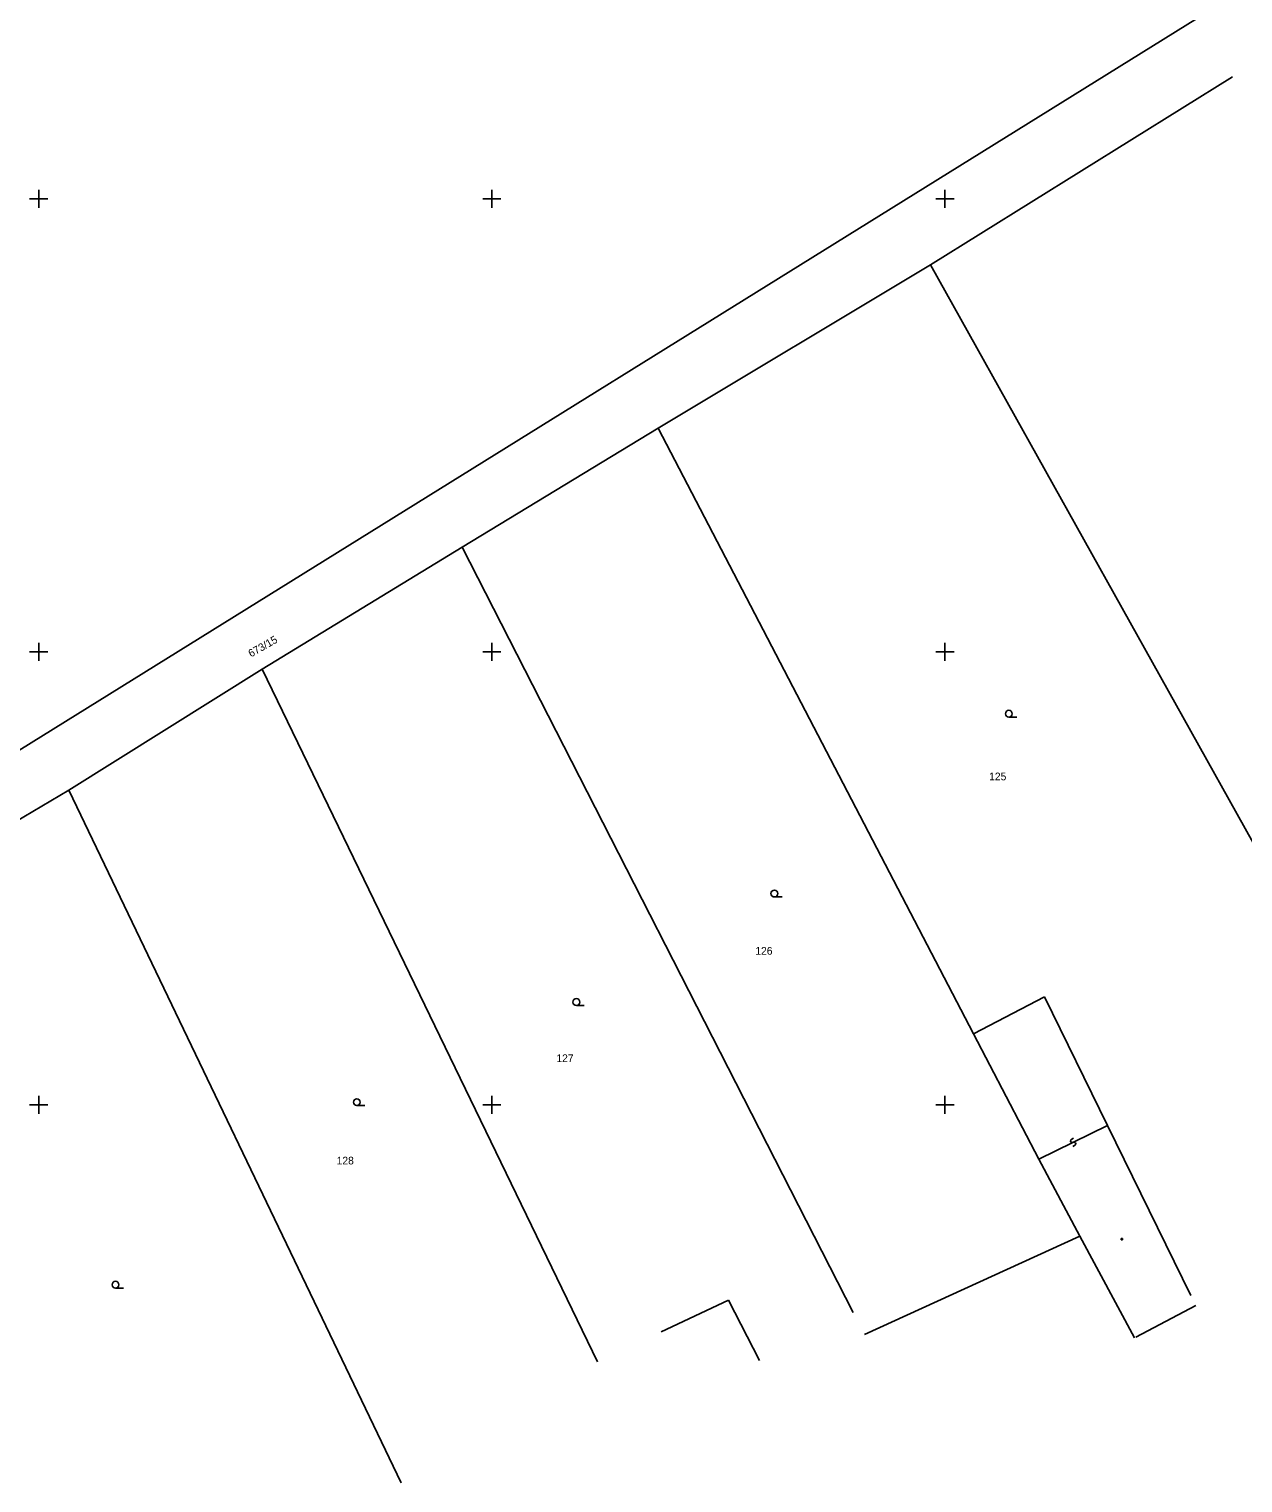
# Model space of a CAD drawing. Extents: x -492811 to -492366, y -1127107 to -1126748.
# Drawn here: x -492480.4 to -492426.8, y -1127096.7 to -1127032.5 of the extents above; entities that cross this region are included whole.
import ezdxf

# ---------------------------------------------------------------- set-up
doc = ezdxf.new("R2010")
doc.units = 0
doc.layers.add('katastrální mapa', color=7, linetype='Continuous')
doc.layers.add('síť', color=7, linetype='Continuous')

msp = doc.modelspace()

# ---------------------------------------------------------------- linework, layer by layer
at = {"layer": 'katastrální mapa'}
for p, q in [((-492495.17, -1127073.23), (-492365.81, -1126992.83)), ((-492440.64, -1127042.91), (-492427.31, -1127034.62)), ((-492452.66, -1127050.13), (-492440.64, -1127042.91)), ((-492440.64, -1127042.91), (-492424.17, -1127072.44)), ((-492461.31, -1127055.38), (-492452.66, -1127050.13)), ((-492452.66, -1127050.13), (-492438.74, -1127076.86)), ((-492470.14, -1127060.76), (-492461.31, -1127055.38)), ((-492461.31, -1127055.38), (-492444.05, -1127089.16)), ((-492478.67, -1127066.1), (-492470.14, -1127060.76)), ((-492470.14, -1127060.76), (-492455.34, -1127091.34)), ((-492437.18, -1127062.88), (-492436.83, -1127062.88)), ((-492491.77, -1127073.86), (-492478.67, -1127066.1)), ((-492478.67, -1127066.1), (-492464, -1127096.69)), ((-492447.53, -1127070.82), (-492447.18, -1127070.82)), ((-492456.27, -1127075.61), (-492455.92, -1127075.61)), ((-492438.74, -1127076.86), (-492435.61, -1127075.23)), ((-492435.61, -1127075.23), (-492432.82, -1127080.91)), ((-492438.74, -1127076.86), (-492435.86, -1127082.4)), ((-492465.96, -1127080.03), (-492465.61, -1127080.03)), ((-492435.86, -1127082.4), (-492432.82, -1127080.91)), ((-492434.32, -1127081.47), (-492434.44, -1127081.55)), ((-492432.82, -1127080.91), (-492429.15, -1127088.41)), ((-492434.44, -1127081.55), (-492434.46, -1127081.6)), ((-492434.46, -1127081.6), (-492434.44, -1127081.64)), ((-492434.44, -1127081.64), (-492434.38, -1127081.65)), ((-492434.38, -1127081.65), (-492434.3, -1127081.66)), ((-492434.24, -1127081.76), (-492434.36, -1127081.84)), ((-492434.3, -1127081.66), (-492434.24, -1127081.67)), ((-492434.24, -1127081.67), (-492434.22, -1127081.71)), ((-492434.22, -1127081.71), (-492434.24, -1127081.76)), ((-492435.86, -1127082.4), (-492434.04, -1127085.8)), ((-492443.55, -1127090.14), (-492434.04, -1127085.8)), ((-492434.04, -1127085.8), (-492431.64, -1127090.29)), ((-492432.23, -1127085.9), (-492432.17, -1127085.9)), ((-492432.23, -1127085.96), (-492432.23, -1127085.9)), ((-492432.17, -1127085.96), (-492432.23, -1127085.96)), ((-492432.17, -1127085.9), (-492432.17, -1127085.96)), ((-492476.61, -1127088.09), (-492476.26, -1127088.09)), ((-492452.53, -1127090.02), (-492449.55, -1127088.62)), ((-492449.55, -1127088.62), (-492448.19, -1127091.28)), ((-492431.58, -1127090.26), (-492428.93, -1127088.85))]:
    msp.add_line(p, q, dxfattribs=at)
for centre in [(-492437.18, -1127062.73), (-492447.53, -1127070.67), (-492456.27, -1127075.46), (-492465.96, -1127079.88), (-492476.61, -1127087.94)]:
    msp.add_circle(centre, 0.15, dxfattribs=at)
at = {"layer": 'síť'}
for p, q in [((-492480, -1127039.6), (-492480, -1127040.4)), ((-492460, -1127039.6), (-492460, -1127040.4)), ((-492440, -1127039.6), (-492440, -1127040.4)), ((-492480.4, -1127040), (-492479.6, -1127040)), ((-492460.4, -1127040), (-492459.6, -1127040)), ((-492440.4, -1127040), (-492439.6, -1127040)), ((-492480, -1127059.6), (-492480, -1127060.4)), ((-492460, -1127059.6), (-492460, -1127060.4)), ((-492440, -1127059.6), (-492440, -1127060.4)), ((-492480.4, -1127060), (-492479.6, -1127060)), ((-492460.4, -1127060), (-492459.6, -1127060)), ((-492440.4, -1127060), (-492439.6, -1127060)), ((-492480, -1127079.6), (-492480, -1127080.4)), ((-492460, -1127079.6), (-492460, -1127080.4)), ((-492440, -1127079.6), (-492440, -1127080.4)), ((-492480.4, -1127080), (-492479.6, -1127080)), ((-492460.4, -1127080), (-492459.6, -1127080)), ((-492440.4, -1127080), (-492439.6, -1127080))]:
    msp.add_line(p, q, dxfattribs=at)

# ---------------------------------------------------------------- texts
at = {"layer": 'katastrální mapa'}
msp.add_text('673/15', height=0.34, rotation=29.79, dxfattribs=at).set_placement((-492470.63, -1127060.25))
for s, p in [('125', (-492438.05, -1127065.67)), ('126', (-492448.37, -1127073.37)), ('127', (-492457.15, -1127078.11)), ('128', (-492466.85, -1127082.63))]:
    msp.add_text(s, height=0.34, dxfattribs=at).set_placement(p)

doc.saveas('drawing.dxf')
